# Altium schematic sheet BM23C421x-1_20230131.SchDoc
size A4
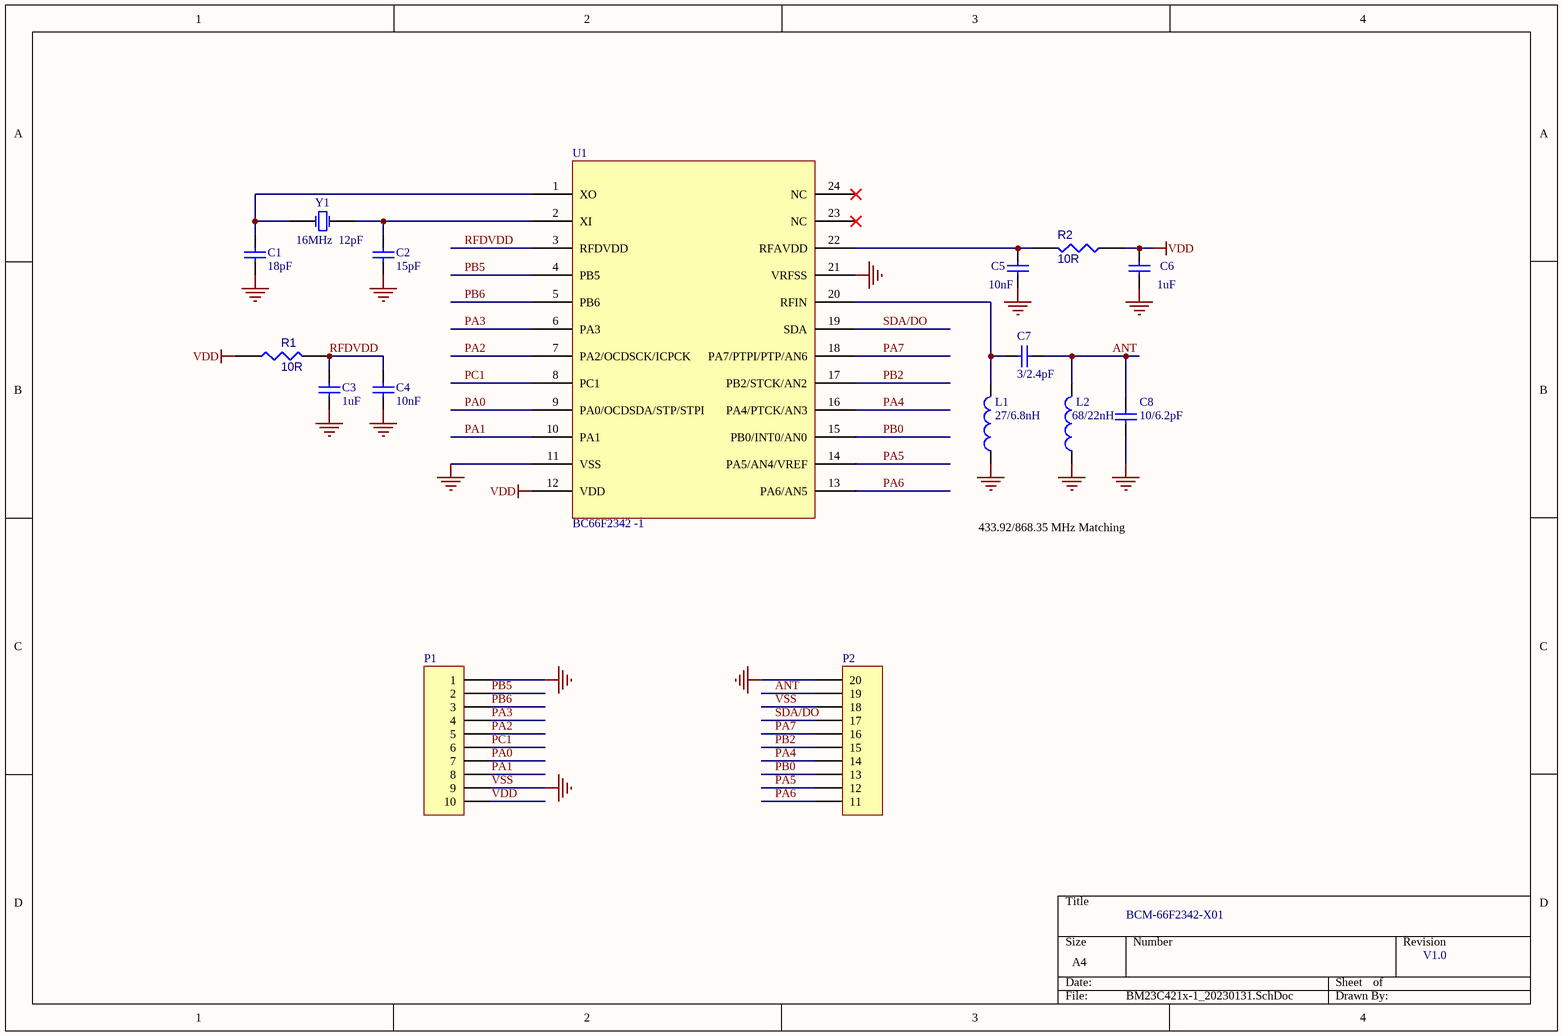
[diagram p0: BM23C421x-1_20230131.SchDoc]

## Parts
C1  value 18pF  [0402C]  (hidden comment: Cap)
C2  value 15pF  [0402C]  (hidden comment: Cap)
C3  value 1uF  [0402C]  (hidden comment: Cap)
C4  value 10nF  [0402C]  (hidden comment: Cap)
C5  value 10nF  [0402C]  (hidden comment: Cap)
C6  value 1uF  [0402C]  (hidden comment: Cap)
C7  value 3/2.4pF  [0402C]  (hidden comment: Cap)
C8  value 10/6.2pF  [0402C]  (hidden comment: Cap)
L1  value 27/6.8nH  [0402C]  (hidden comment: Inductor)
L2  value 68/22nH  [0402C]  (hidden comment: Inductor)
P1  Header 10  [YPK-10PIN_1.27mm]  (value not drawn)
P2  Header 10  [YPK-10PIN_1.27mm]  (value not drawn)
R1  10R  [0402C]
R2  10R  [0402C]
U1  BC66F2342 -1  [24SSOP-EP]
Y1  16MHz  12pF  [XTAL-SMD3225]

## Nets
VDD: C6.1 P1.10 R1.1 R2.1 U1.12(VDD)
VSS: C1.2 C2.2 C3.2 C4.2 C5.2 C6.2 C8.1 L1.1 L2.1 P1.1 P1.9 P2.18 P2.20 U1.11(VSS) U1.21(VRFSS)  [also labelled GND]
ANT: C7.2 C8.2 L2.2 P2.19
PA0: P1.7 U1.9(PA0/OCDSDA/STP/STPI)
PA1: P1.8 U1.10(PA1)
PA2: P1.5 U1.7(PA2/OCDSCK/ICPCK)
PA3: P1.4 U1.6(PA3)
PA4: P2.14 U1.16(PA4/PTCK/AN3)
PA5: P2.12 U1.14(PA5/AN4/VREF)
PA6: P2.11 U1.13(PA6/AN5)
PA7: P2.16 U1.18(PA7/PTPI/PTP/AN6)
PB0: P2.13 U1.15(PB0/INT0/AN0)
PB2: P2.15 U1.17(PB2/STCK/AN2)
PB5: P1.2 U1.4(PB5)
PB6: P1.3 U1.5(PB6)
PC1: P1.6 U1.8(PC1)
RFDVDD: C3.1 C4.1 R1.2 U1.3(RFDVDD)
SDA/DO: P2.17 U1.19(SDA)
NetC1_1: C1.1 U1.1(XO) Y1.3(OSC2)
NetC2_1: C2.1 U1.2(XI) Y1.1(OSC1)
NetC5_1: C5.1 R2.2 U1.22(RFAVDD)
NetC7_1: C7.1 L1.2 U1.20(RFIN)

Not connected (* = marked no-connect by the designer): U1 23(NC)* 24(NC)*

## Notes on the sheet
- 433.92/868.35 MHz Matching
- BCM-66F2342-X01
- V1.0

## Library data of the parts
C1-C8 = Cap: Capacitor
L1 L2 = Inductor: Code_IEC: 1005
P1 P2 = Header 10: Header, 10-Pin
R1 R2 = RES1
U1 = BC66F2342
Y1 = XTAL: Crystal Oscillator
